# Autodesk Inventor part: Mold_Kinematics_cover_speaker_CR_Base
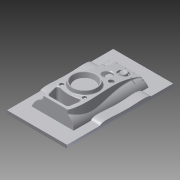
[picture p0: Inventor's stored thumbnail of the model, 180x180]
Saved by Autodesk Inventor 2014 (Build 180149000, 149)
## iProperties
Created: 2009-12
Part Number: Mold_Kinematics_cover_speaker_CR_Base
Document SubType Name: Modeling
Designer: gaom
Density: 1 g/cm^3
Material: Generic
Appearance: Default
Author: gaom
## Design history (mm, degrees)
node "Mold_Kinematics_cover_speaker_MP"
feature "Solid3::Mold_Kinematics_cover_speaker_MP"
tag "TaggingFeature1"
body "Solid1"
